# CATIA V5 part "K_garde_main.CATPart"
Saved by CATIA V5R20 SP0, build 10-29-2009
Part number: garde_main
Bounding box of the stored display mesh (mm): x -20 to 20, y -74.878 to 156.736, z -85 to 10
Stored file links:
  G:\Khaled_CFAO_2011\SIL\SIL_GR2\mdupuis\Khaled\CAD_ThinkMOTION\K_garde_main.CATPart
  G:\Dupuis_Maxime_Thinkmotion_CFAO\assemblage.CATProduct
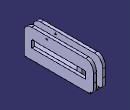
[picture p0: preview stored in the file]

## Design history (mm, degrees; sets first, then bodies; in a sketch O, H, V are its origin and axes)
Set1
  Plane1: linked copy from another document
  Point1: linked copy from another document
  DatumCurve1: linked copy from another document
  Point2: linked copy from another document
Body1 (main body)
  Sketch1 on Plane1, origin (0, 0, -30), H (1, 0, 0), V (0, 1, 0)
    line L1 (10, 107.5) -> (-10, 107.5)
    line L2 (-10, 107.5) -> (-10, 92.5)
    line L3 (-10, 92.5) -> (10, 92.5)
    line L4 (10, 92.5) -> (10, 107.5)
    reference projected point E1 (0, 100) from Point1
    reference projected point E2 (0, 100) from Point1
    length L1 = 20
    distance L2 E1 = 10
    distance L1 E2 = 7.5
    length L4 = 15
    horizontal: L1 H, L3 H
    vertical: L2 V, L4 V
  Pad1: profile Sketch1, direction (0, 0, -1), length 50
  Sketch2 on face of Pad1 from Sketch1.L4, origin (10, 0, 0), H (0, 1, 0), V (0, 0, 1)
    line L1 (145.1217, -80) -> (-74.8783, -80)
    line L2 (-74.8783, -80) -> (-74.8783, -13.7847)
    line L3 (156.6615, -48.6826) -> (156.6615, -22.278)
    line L4 (-50, 10) -> (130, 10)
    connectcurve C1
    connectcurve C2
    line L5 (-50, -50.2395) -> (130, -50.2395)
    line L6 (130, -50.2395) -> (130, -30)
    line L7 (-50, -50.2395) -> (-50, -30.2395)
    line L8 (-28.0098, -26.2395) -> (121.9902, -26.2395)
    connectcurve C3
    connectcurve C4
    connectcurve C5
    length L1 = 220
    distance L8 L5 = 24
    horizontal: L1 H, L4 H, L5 H, L8 H
    vertical: L2 V, L3 V, L6 V, L7 V
  Pad2: profile Sketch2, direction (1, 0, 0), length 10
  Mirror1: of Pad2, about yz-plane
  Sketch3 on face of Mirror1, origin (0, 0, -80), H (1, 0, 0), V (0, -1, 0)
    point P1 (-20, 74.8783)
    line L1 (-20, 74.8783) -> (20, 74.8783)
    line L2 (20, 74.8783) -> (20, -145.1217)
    line L3 (20, -145.1217) -> (-20, -145.1217)
    line L4 (-20, -145.1217) -> (-20, 74.8783)
    reference projected point E1 (-20, 74.8783) from vertex [face of Mirror1 | face of Mirror1 | face of Mirror1]
    length L2 = 220
    length L1 = 40
    horizontal: L1 H, L3 H
    vertical: L2 V, L4 V
    coincidence: P1 E1
  Pad3: profile Sketch3, direction (0, 0, -1), length 5
  Sketch4 on face of Pad3, origin (20, 5.4324, -4.1138), H (0, 1, 0), V (0, 0, 1)
    point P1 (-5.4324, 4.1138)
    reference projected point E1 (-5.4324, 4.1138) from Point2
    coincidence: P1 E1
  Hole1: placed by Sketch4, at (20, 0, 0) direction (-1, 0, 0), diameter 5, depth 10
  Mirror2: of Hole1, about yz-plane
  Sketch5 on face of Pad1 from Sketch1.L3, origin (0, 92.5, 0), H (1, 0, 0), V (0, 0, 1)
    line L1 (-10, -50) -> (10, -50)
    line L2 (10, -50) -> (10, -80)
    line L3 (10, -80) -> (-10, -80)
    line L4 (-10, -80) -> (-10, -50)
    reference projected line E1 (-10, -13.7847) -> (-10, -80) from edge [face of Pad3 | face of Mirror1]
    length L3 = 20
    distance L4 E1 = 0
    horizontal: L1 H, L3 H
    vertical: L2 V, L4 V
  Pad4: profile Sketch5, direction (0, -1, 0), length 167
  DatumSurface1
  Sketch6 on start face of Pad1, origin (0, 0, -30), H (1, 0, 0), V (0, 1, 0)
    circle A1 centre (0, 100) radius 2.5
    point P1 (0, 100)
    radius A1 = 2.5
    coincidence: P1 V
  Pocket1: profile Sketch6, direction (0, 0, -1), length 0.5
